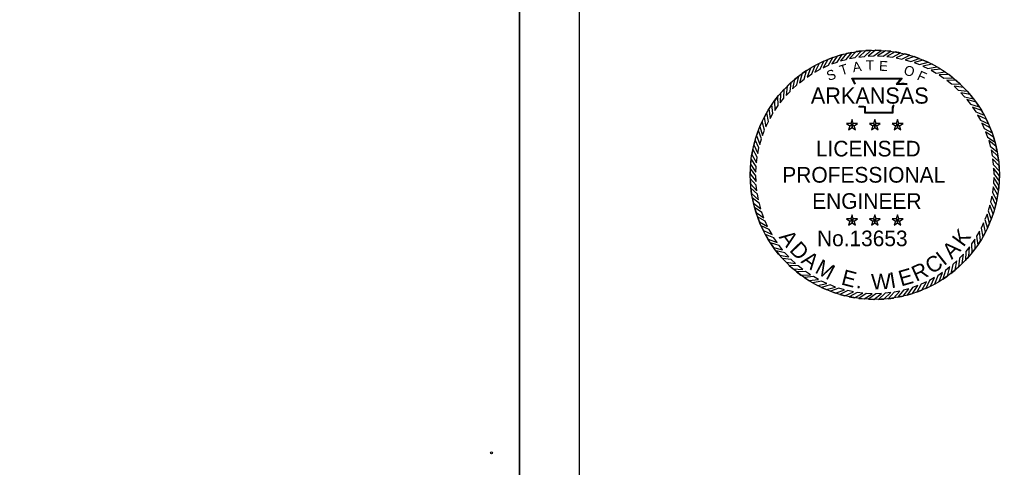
# Model space of a CAD drawing. Extents: x 759422 to 1467391, y 1662254 to 1691810.
# Drawn here: x 1466918.7 to 1467390.5, y 1691236.2 to 1691451.9 of the extents above; entities that cross this region are included whole.
import ezdxf

# ---------------------------------------------------------------- set-up
doc = ezdxf.new("R2010")
doc.units = 0
for name, color, linetype in [('G-ANNO-STMP', 7, 'Continuous'), ('G-Border-Paper', 7, 'Continuous'), ('G-Border-Sheet', 7, 'Continuous'), ('G-No Plot-Anchor', 7, 'Continuous'), ('G-No Plot-Border-1', 7, 'Continuous'), ('G-No Plot-Stamp-1', 7, 'Continuous')]:
    doc.layers.add(name, color=color, linetype=linetype)

msp = doc.modelspace()

# ---------------------------------------------------------------- linework, layer by layer
at = {"layer": 'G-ANNO-STMP'}
for points in [[(1467310.32, 1691433.67), (1467307.91, 1691432.76), (1467305.64, 1691428.75), (1467308.18, 1691429.9)], [(1467314.81, 1691435.08), (1467312.34, 1691434.36), (1467309.77, 1691430.54), (1467312.39, 1691431.49)], [(1467319.41, 1691436.13), (1467316.88, 1691435.6), (1467314.02, 1691432), (1467316.71, 1691432.74)], [(1467324.07, 1691436.82), (1467321.51, 1691436.49), (1467318.37, 1691433.13), (1467321.11, 1691433.65)], [(1467328.77, 1691437.14), (1467326.19, 1691437.01), (1467322.8, 1691433.9), (1467325.57, 1691434.21)], [(1467333.48, 1691437.09), (1467330.9, 1691437.16), (1467327.28, 1691434.33), (1467330.06, 1691434.42)], [(1467338.17, 1691436.67), (1467335.61, 1691436.95), (1467331.77, 1691434.41), (1467334.56, 1691434.28)], [(1467342.82, 1691435.88), (1467340.28, 1691436.36), (1467336.26, 1691434.13), (1467339.03, 1691433.78)], [(1467347.39, 1691434.73), (1467344.9, 1691435.41), (1467340.71, 1691433.5), (1467343.44, 1691432.94)], [(1467351.85, 1691433.23), (1467349.42, 1691434.1), (1467345.1, 1691432.52), (1467347.78, 1691431.75)], [(1467301.73, 1691429.82), (1467299.49, 1691428.54), (1467297.88, 1691424.23), (1467300.21, 1691425.76)], [(1467305.95, 1691431.92), (1467303.62, 1691430.81), (1467301.67, 1691426.64), (1467304.11, 1691427.99)], [(1467356.19, 1691431.38), (1467353.83, 1691432.44), (1467349.4, 1691431.21), (1467352.01, 1691430.22)], [(1467360.36, 1691429.2), (1467358.1, 1691430.43), (1467353.58, 1691429.56), (1467356.1, 1691428.37)], [(1467293.84, 1691424.68), (1467291.83, 1691423.06), (1467290.92, 1691418.55), (1467292.98, 1691420.43)], [(1467297.68, 1691427.41), (1467295.55, 1691425.95), (1467294.29, 1691421.53), (1467296.49, 1691423.24)], [(1467364.35, 1691426.69), (1467362.19, 1691428.1), (1467357.62, 1691427.58), (1467360.04, 1691426.2)], [(1467368.13, 1691423.88), (1467366.09, 1691425.46), (1467361.49, 1691425.3), (1467363.8, 1691423.73)], [(1467290.23, 1691421.66), (1467288.35, 1691419.88), (1467287.79, 1691415.32), (1467289.7, 1691417.35)], [(1467371.68, 1691420.79), (1467369.77, 1691422.52), (1467365.18, 1691422.72), (1467367.35, 1691420.97)], [(1467374.98, 1691417.42), (1467373.21, 1691419.29), (1467368.64, 1691419.85), (1467370.68, 1691417.95)], [(1467283.76, 1691414.81), (1467282.19, 1691412.77), (1467282.35, 1691408.17), (1467283.91, 1691410.48)], [(1467286.86, 1691418.36), (1467285.13, 1691416.45), (1467284.93, 1691411.85), (1467286.67, 1691414.03)], [(1467378, 1691413.8), (1467376.38, 1691415.81), (1467371.87, 1691416.73), (1467373.75, 1691414.67)], [(1467280.95, 1691411.03), (1467279.54, 1691408.87), (1467280.06, 1691404.3), (1467281.44, 1691406.72)], [(1467380.73, 1691409.96), (1467379.27, 1691412.09), (1467374.85, 1691413.36), (1467376.56, 1691411.16)], [(1467383.15, 1691405.92), (1467381.86, 1691408.16), (1467377.55, 1691409.77), (1467379.09, 1691407.44)], [(1467278.45, 1691407.04), (1467277.21, 1691404.77), (1467278.09, 1691400.26), (1467279.27, 1691402.78)], [(1467385.24, 1691401.7), (1467384.14, 1691404.03), (1467379.97, 1691405.97), (1467381.31, 1691403.53)], [(1467276.26, 1691402.86), (1467275.21, 1691400.51), (1467276.44, 1691396.08), (1467277.42, 1691398.68)], [(1467319.51, 1691401.05), (1467318.9, 1691401.9), (1467316.9, 1691401.9), (1467318.52, 1691400.73)], [(1467319.51, 1691401.05), (1467318.52, 1691400.73), (1467317.9, 1691398.84), (1467319.51, 1691400.01)], [(1467319.51, 1691401.05), (1467320.13, 1691401.9), (1467319.51, 1691403.8), (1467318.9, 1691401.9)], [(1467319.51, 1691401.05), (1467320.51, 1691400.73), (1467322.12, 1691401.9), (1467320.13, 1691401.9)], [(1467319.51, 1691401.05), (1467319.51, 1691400.01), (1467321.12, 1691398.84), (1467320.51, 1691400.73)], [(1467330.48, 1691401.05), (1467329.87, 1691401.9), (1467327.88, 1691401.9), (1467329.49, 1691400.73)], [(1467330.48, 1691401.05), (1467329.49, 1691400.73), (1467328.87, 1691398.84), (1467330.48, 1691400.01)], [(1467330.48, 1691401.05), (1467331.1, 1691401.9), (1467330.48, 1691403.8), (1467329.87, 1691401.9)], [(1467330.48, 1691401.05), (1467331.48, 1691400.73), (1467333.09, 1691401.9), (1467331.1, 1691401.9)], [(1467330.48, 1691401.05), (1467330.48, 1691400.01), (1467332.1, 1691398.84), (1467331.48, 1691400.73)], [(1467341.46, 1691401.05), (1467340.84, 1691401.9), (1467338.85, 1691401.9), (1467340.46, 1691400.73)], [(1467341.46, 1691401.05), (1467340.46, 1691400.73), (1467339.84, 1691398.84), (1467341.46, 1691400.01)], [(1467341.46, 1691401.05), (1467342.07, 1691401.9), (1467341.46, 1691403.8), (1467340.84, 1691401.9)], [(1467341.46, 1691401.05), (1467342.45, 1691400.73), (1467344.07, 1691401.9), (1467342.07, 1691401.9)], [(1467341.46, 1691401.05), (1467341.46, 1691400.01), (1467343.07, 1691398.84), (1467342.45, 1691400.73)], [(1467387, 1691397.33), (1467386.08, 1691399.74), (1467382.08, 1691402), (1467383.22, 1691399.46)], [(1467274.41, 1691398.53), (1467273.55, 1691396.1), (1467275.12, 1691391.78), (1467275.9, 1691394.45)], [(1467388.41, 1691392.83), (1467387.68, 1691395.31), (1467383.87, 1691397.88), (1467384.81, 1691395.26)], [(1467272.91, 1691394.06), (1467272.24, 1691391.57), (1467274.14, 1691387.39), (1467274.71, 1691390.12)], [(1467389.46, 1691388.24), (1467388.93, 1691390.76), (1467385.33, 1691393.63), (1467386.06, 1691390.94)], [(1467271.76, 1691389.5), (1467271.29, 1691386.96), (1467273.52, 1691382.94), (1467273.86, 1691385.7)], [(1467390.14, 1691383.58), (1467389.81, 1691386.14), (1467386.45, 1691389.27), (1467386.97, 1691386.53)], [(1467270.98, 1691384.85), (1467270.7, 1691382.28), (1467273.24, 1691378.45), (1467273.37, 1691381.23)], [(1467390.46, 1691378.88), (1467390.33, 1691381.45), (1467387.23, 1691384.84), (1467387.53, 1691382.07)], [(1467270.56, 1691380.16), (1467270.48, 1691377.58), (1467273.31, 1691373.95), (1467273.23, 1691376.74)], [(1467390.41, 1691374.16), (1467390.49, 1691376.74), (1467387.66, 1691380.37), (1467387.74, 1691377.58)], [(1467270.5, 1691375.45), (1467270.63, 1691372.87), (1467273.74, 1691369.48), (1467273.43, 1691372.25)], [(1467389.99, 1691369.47), (1467390.27, 1691372.04), (1467387.73, 1691375.87), (1467387.6, 1691373.09)], [(1467270.82, 1691370.75), (1467271.16, 1691368.19), (1467274.52, 1691365.05), (1467274, 1691367.79)], [(1467388.06, 1691360.26), (1467388.73, 1691362.75), (1467386.82, 1691366.93), (1467386.26, 1691364.2)], [(1467389.21, 1691364.83), (1467389.68, 1691367.36), (1467387.45, 1691371.39), (1467387.1, 1691368.62)], [(1467271.51, 1691366.08), (1467272.04, 1691363.56), (1467275.64, 1691360.7), (1467274.91, 1691363.38)], [(1467386.55, 1691355.79), (1467387.42, 1691358.22), (1467385.85, 1691362.54), (1467385.07, 1691359.87)], [(1467272.56, 1691361.49), (1467273.29, 1691359.02), (1467277.1, 1691356.44), (1467276.16, 1691359.07)], [(1467319.51, 1691355.11), (1467320.13, 1691355.96), (1467319.51, 1691357.85), (1467318.9, 1691355.96)], [(1467330.48, 1691355.11), (1467331.1, 1691355.96), (1467330.48, 1691357.85), (1467329.87, 1691355.96)], [(1467341.46, 1691355.11), (1467342.07, 1691355.96), (1467341.46, 1691357.85), (1467340.84, 1691355.96)], [(1467384.7, 1691351.46), (1467385.76, 1691353.81), (1467384.53, 1691358.25), (1467383.55, 1691355.64)], [(1467273.97, 1691357), (1467274.89, 1691354.58), (1467278.89, 1691352.32), (1467277.74, 1691354.86)], [(1467319.51, 1691355.11), (1467318.9, 1691355.96), (1467316.9, 1691355.96), (1467318.52, 1691354.79)], [(1467319.51, 1691355.11), (1467318.52, 1691354.79), (1467317.9, 1691352.89), (1467319.51, 1691354.06)], [(1467319.51, 1691355.11), (1467320.51, 1691354.79), (1467322.12, 1691355.96), (1467320.13, 1691355.96)], [(1467319.51, 1691355.11), (1467319.51, 1691354.06), (1467321.12, 1691352.89), (1467320.51, 1691354.79)], [(1467330.48, 1691355.11), (1467329.87, 1691355.96), (1467327.88, 1691355.96), (1467329.49, 1691354.79)], [(1467330.48, 1691355.11), (1467329.49, 1691354.79), (1467328.87, 1691352.89), (1467330.48, 1691354.06)], [(1467330.48, 1691355.11), (1467331.48, 1691354.79), (1467333.09, 1691355.96), (1467331.1, 1691355.96)], [(1467330.48, 1691355.11), (1467330.48, 1691354.06), (1467332.1, 1691352.89), (1467331.48, 1691354.79)], [(1467341.46, 1691355.11), (1467340.84, 1691355.96), (1467338.85, 1691355.96), (1467340.46, 1691354.79)], [(1467341.46, 1691355.11), (1467340.46, 1691354.79), (1467339.84, 1691352.89), (1467341.46, 1691354.06)], [(1467341.46, 1691355.11), (1467342.45, 1691354.79), (1467344.07, 1691355.96), (1467342.07, 1691355.96)], [(1467341.46, 1691355.11), (1467341.46, 1691354.06), (1467343.07, 1691352.89), (1467342.45, 1691354.79)], [(1467382.52, 1691347.28), (1467383.76, 1691349.55), (1467382.88, 1691354.06), (1467381.69, 1691351.54)], [(1467275.73, 1691352.62), (1467276.83, 1691350.29), (1467281, 1691348.35), (1467279.66, 1691350.79)], [(1467277.82, 1691348.4), (1467279.11, 1691346.17), (1467283.41, 1691344.55), (1467281.88, 1691346.88)], [(1467380.02, 1691343.29), (1467381.43, 1691345.45), (1467380.91, 1691350.02), (1467379.53, 1691347.6)], [(1467280.24, 1691344.36), (1467281.7, 1691342.23), (1467286.12, 1691340.96), (1467284.41, 1691343.16)], [(1467377.21, 1691339.51), (1467378.78, 1691341.56), (1467378.62, 1691346.15), (1467377.06, 1691343.85)], [(1467282.97, 1691340.52), (1467284.59, 1691338.51), (1467289.09, 1691337.59), (1467287.22, 1691339.65)], [(1467370.74, 1691332.67), (1467372.62, 1691334.44), (1467373.18, 1691339), (1467371.27, 1691336.97)], [(1467374.11, 1691335.96), (1467375.84, 1691337.88), (1467376.04, 1691342.47), (1467374.3, 1691340.29)], [(1467285.99, 1691336.9), (1467287.76, 1691335.03), (1467292.33, 1691334.47), (1467290.29, 1691336.37)], [(1467367.13, 1691329.64), (1467369.14, 1691331.26), (1467370.05, 1691335.77), (1467367.99, 1691333.89)], [(1467289.29, 1691333.54), (1467291.2, 1691331.81), (1467295.79, 1691331.6), (1467293.62, 1691333.35)], [(1467292.83, 1691330.44), (1467294.88, 1691328.86), (1467299.47, 1691329.02), (1467297.17, 1691330.59)], [(1467359.24, 1691324.5), (1467361.48, 1691325.78), (1467363.09, 1691330.09), (1467360.76, 1691328.56)], [(1467363.29, 1691326.92), (1467365.42, 1691328.37), (1467366.68, 1691332.79), (1467364.48, 1691331.08)], [(1467296.62, 1691327.63), (1467298.78, 1691326.22), (1467303.35, 1691326.74), (1467300.93, 1691328.12)], [(1467300.61, 1691325.12), (1467302.87, 1691323.89), (1467307.39, 1691324.77), (1467304.86, 1691325.95)], [(1467350.65, 1691320.65), (1467353.06, 1691321.57), (1467355.33, 1691325.57), (1467352.79, 1691324.42)], [(1467355.02, 1691322.4), (1467357.35, 1691323.51), (1467359.3, 1691327.68), (1467356.85, 1691326.33)], [(1467304.78, 1691322.94), (1467307.14, 1691321.89), (1467311.57, 1691323.11), (1467308.96, 1691324.1)], [(1467309.12, 1691321.09), (1467311.55, 1691320.22), (1467315.87, 1691321.8), (1467313.19, 1691322.57)], [(1467313.58, 1691319.59), (1467316.07, 1691318.91), (1467320.26, 1691320.82), (1467317.53, 1691321.39)], [(1467318.15, 1691318.44), (1467320.69, 1691317.96), (1467324.71, 1691320.19), (1467321.94, 1691320.54)], [(1467322.8, 1691317.65), (1467325.36, 1691317.38), (1467329.2, 1691319.91), (1467326.41, 1691320.05)], [(1467327.49, 1691317.23), (1467330.07, 1691317.16), (1467333.69, 1691319.99), (1467330.91, 1691319.9)], [(1467332.2, 1691317.18), (1467334.78, 1691317.31), (1467338.17, 1691320.42), (1467335.4, 1691320.11)], [(1467336.9, 1691317.5), (1467339.46, 1691317.83), (1467342.6, 1691321.2), (1467339.86, 1691320.67)], [(1467341.56, 1691318.19), (1467344.09, 1691318.72), (1467346.95, 1691322.32), (1467344.26, 1691321.58)], [(1467346.15, 1691319.24), (1467348.63, 1691319.97), (1467351.2, 1691323.78), (1467348.58, 1691322.83)]]:
    msp.add_lwpolyline(points, close=True, dxfattribs=at)
for points in [[(1467320.87, 1691420.71), (1467319.47, 1691423.74), (1467343.68, 1691423.75), (1467341.65, 1691421.21), (1467343.3, 1691421.23), (1467344.67, 1691421.25), (1467346.04, 1691421.1)], [(1467321.22, 1691420.87), (1467320.07, 1691423.36), (1467342.88, 1691423.37), (1467340.85, 1691420.82), (1467343.3, 1691420.85), (1467344.65, 1691420.87), (1467346, 1691420.72)], [(1467339.86, 1691410.57), (1467339.45, 1691410.23), (1467339.31, 1691409.73), (1467339.17, 1691408.48), (1467339.17, 1691406.8), (1467325.66, 1691406.8), (1467325.66, 1691409.06), (1467325.66, 1691409.56), (1467325.12, 1691409.73), (1467323.19, 1691409.73), (1467322.85, 1691410.25)], [(1467339.62, 1691410.87), (1467339.11, 1691410.45), (1467338.93, 1691409.8), (1467338.79, 1691408.5), (1467338.79, 1691407.19), (1467326.05, 1691407.19), (1467326.05, 1691409.06), (1467326.05, 1691409.85), (1467325.17, 1691410.11), (1467323.4, 1691410.11), (1467323.17, 1691410.46)]]:
    msp.add_lwpolyline(points, dxfattribs=at)
at = {"layer": 'G-Border-Paper'}
msp.add_lwpolyline([(1467188.26, 1691786.2), (1465488.26, 1691786.2), (1465488.26, 1690686.2), (1467188.26, 1690686.2)], close=True, dxfattribs=at)
at = {"layer": 'G-Border-Sheet'}
msp.add_line((1467159.42, 1690715.04), (1467159.42, 1691757.36), dxfattribs=at)
at = {"layer": 'G-No Plot-Anchor'}
msp.add_circle((1467145.92, 1691243.24), 0.5, dxfattribs=at)
at = {"layer": 'G-No Plot-Border-1'}
msp.add_lwpolyline([(1465564.06, 1691229.74), (1465564.06, 1691757.36), (1466762.07, 1691757.36), (1466762.07, 1691707.82), (1466960.32, 1691707.82), (1466960.32, 1691692.32), (1467031.92, 1691692.32), (1467031.92, 1691544.82), (1467159.42, 1691544.82), (1467159.42, 1691229.74)], close=True, dxfattribs=at)
at = {"layer": 'G-No Plot-Stamp-1'}
msp.add_circle((1467330.48, 1691377.16), 60, dxfattribs=at)

# ---------------------------------------------------------------- texts
at = {"layer": 'G-ANNO-STMP'}
for s, height, rotation, p in [('T', 4.77, 16.9015, (1467314.34, 1691425.02)), ('A', 4.77, 8.6788, (1467320.13, 1691426.54)), ('T', 4.77, 1.4789, (1467326.3, 1691427.49)), ('E', 4.77, 356.672, (1467332.41, 1691427.34)), ('O', 4.77, 341.2218, (1467344, 1691425.7)), ('S', 4.77, 19.7726, (1467308.27, 1691422.3)), ('F', 4.77, 335.3628, (1467350.43, 1691423.19)), ('A', 7.54, 305.982, (1467284.06, 1691347.13)), ('K', 7.54, 53.8471, (1467373.21, 1691342.05)), ('D', 7.54, 314.3022, (1467289.01, 1691340.61)), ('A', 7.54, 45.185, (1467367.55, 1691336.14)), ('A', 7.54, 322.6223, (1467294.6, 1691335.09)), ('I', 7.54, 38.4057, (1467363.75, 1691333.07)), ('M', 7.54, 331.7969, (1467301.19, 1691330.22)), ('R', 7.54, 24.1616, (1467350.37, 1691325.57)), ('C', 7.54, 32.1396, (1467357.76, 1691329.09)), ('E', 7.54, 345.2782, (1467313.9, 1691324.43)), ('W', 7.54, 2.1127, (1467328.89, 1691321.85)), ('I', 7.54, 9.5753, (1467338.36, 1691322.5)), ('E', 7.54, 16.0125, (1467343.17, 1691323.36)), ('.', 7.54, 350.8583, (1467321.22, 1691322.73))]:
    msp.add_text(s, height=height, rotation=rotation, dxfattribs=at).set_placement(p)
for s, height, p in [('ARKANSAS', 7.792, (1467299.69, 1691411.44)), ('LICENSED', 7.543, (1467302.11, 1691386)), ('PROFESSIONAL', 7.5433, (1467285.94, 1691373.39)), ('ENGINEER', 7.543, (1467300.31, 1691360.77)), ('No.13653', 7.514, (1467302.69, 1691342.79))]:
    msp.add_text(s, height=height, dxfattribs=at).set_placement(p)

doc.saveas('drawing.dxf')
